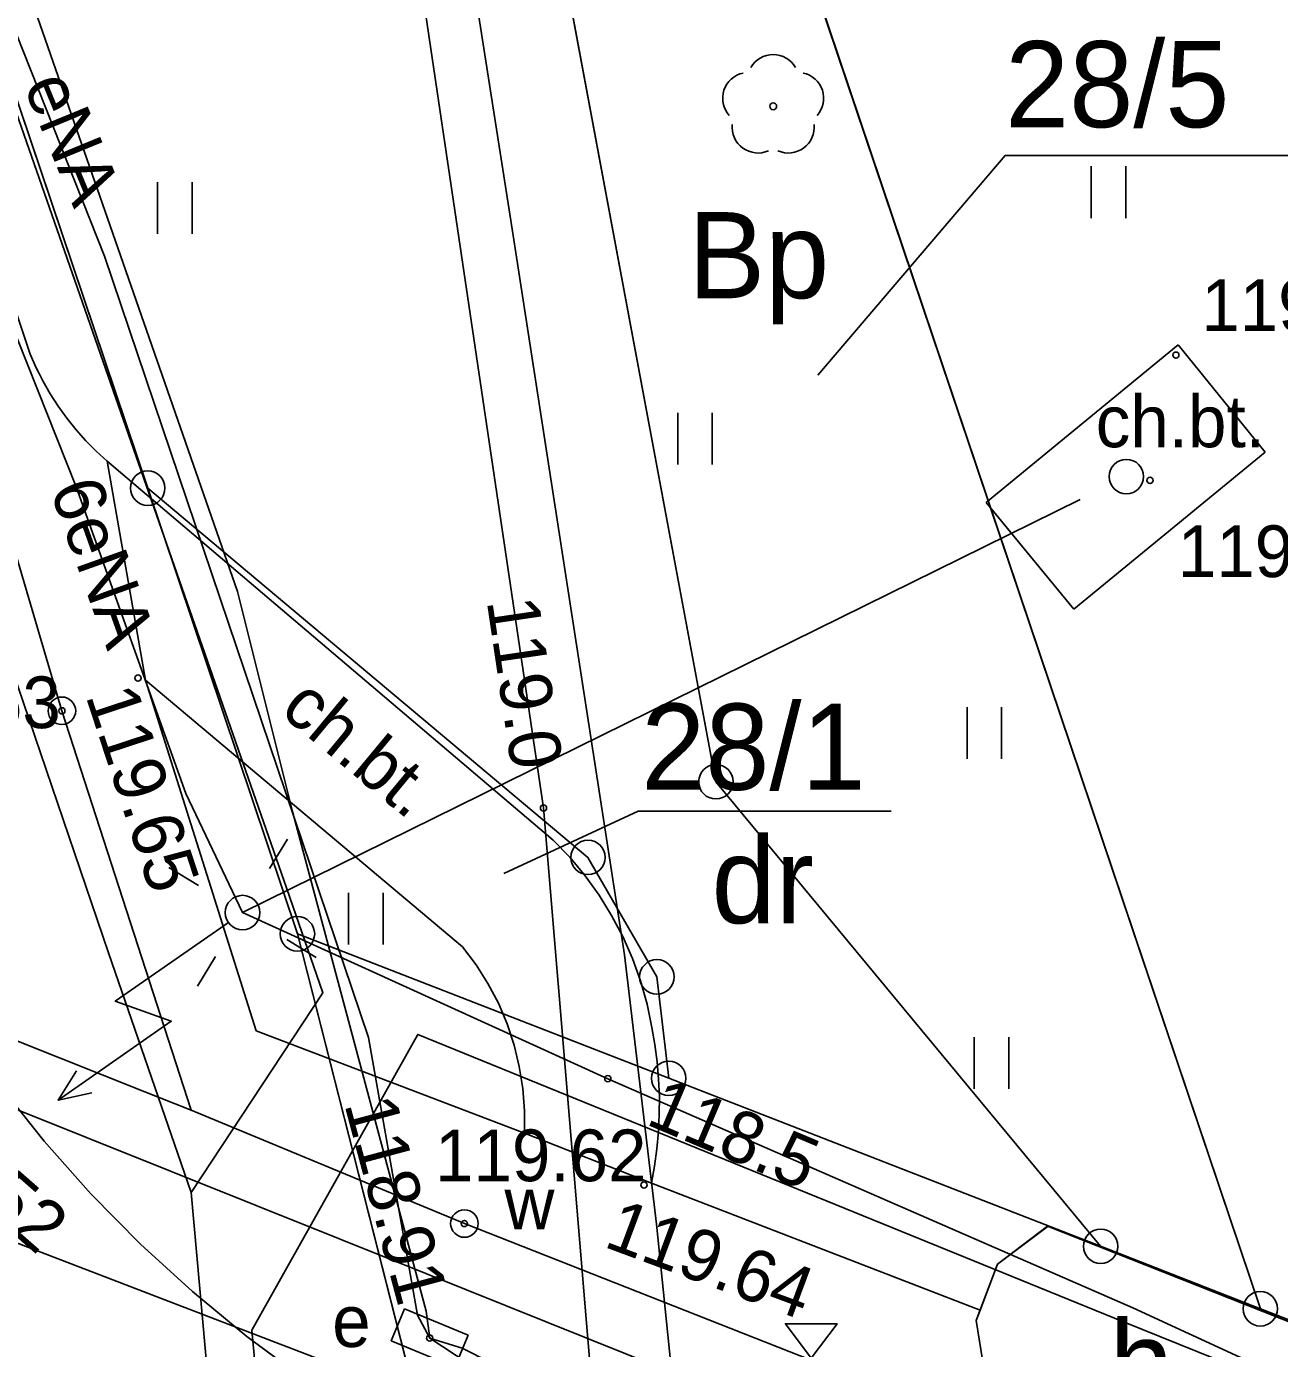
# Model space of a CAD drawing. Extents: x 6432121 to 6432331, y 5662538 to 5662686.
# Drawn here: x 6432285.88 to 6432304.05, y 5662571.21 to 5662590.39 of the extents above; entities that cross this region are included whole.
import ezdxf

# ---------------------------------------------------------------- set-up
doc = ezdxf.new("R2010")
doc.units = 0
for name, color, linetype in [('Warstwa 1', 7, 'Continuous'), ('Warstwa 10', 7, 'Continuous'), ('Warstwa 11', 7, 'Continuous'), ('Warstwa 12', 7, 'Continuous'), ('Warstwa 13', 7, 'Continuous'), ('Warstwa 14', 7, 'Continuous'), ('Warstwa 15', 7, 'Continuous'), ('Warstwa 2', 7, 'Continuous'), ('Warstwa 23', 7, 'Continuous'), ('Warstwa 25', 7, 'Continuous'), ('Warstwa 3', 7, 'Continuous'), ('Warstwa 4', 7, 'Continuous'), ('Warstwa 40', 7, 'Continuous'), ('Warstwa 5', 7, 'Continuous'), ('Warstwa 6', 7, 'Continuous'), ('Warstwa 8', 7, 'Continuous'), ('Warstwa 9', 7, 'Continuous')]:
    doc.layers.add(name, color=color, linetype=linetype)

msp = doc.modelspace()

# ---------------------------------------------------------------- linework, layer by layer
at = {"layer": 'Warstwa 1'}
for p, q in [((6432267.75, 5662642.76), (6432287.64, 5662583.69)), ((6432267.75, 5662642.76), (6432287.64, 5662583.69)), ((6432289.26, 5662614.9), (6432303.776, 5662571.783)), ((6432289.26, 5662614.9), (6432295.88, 5662579.43)), ((6432289.26, 5662614.9), (6432295.88, 5662579.43)), ((6432289.26, 5662614.9), (6432303.776, 5662571.783)), ((6432287.64, 5662583.69), (6432289.811, 5662577.223)), ((6432287.64, 5662583.69), (6432294.025, 5662578.332)), ((6432287.64, 5662583.69), (6432294.025, 5662578.332)), ((6432287.64, 5662583.69), (6432289.811, 5662577.223)), ((6432295.88, 5662579.43), (6432301.46, 5662572.69)), ((6432295.88, 5662579.43), (6432301.46, 5662572.69)), ((6432294.025, 5662578.332), (6432295.024, 5662576.599)), ((6432294.025, 5662578.332), (6432295.024, 5662576.599)), ((6432289.811, 5662577.223), (6432295.196, 5662575.127)), ((6432289.811, 5662577.223), (6432295.199, 5662556.053)), ((6432289.811, 5662577.223), (6432295.196, 5662575.127)), ((6432289.811, 5662577.223), (6432295.199, 5662556.053)), ((6432295.024, 5662576.599), (6432295.196, 5662575.127)), ((6432295.024, 5662576.599), (6432295.196, 5662575.127)), ((6432295.196, 5662575.127), (6432301.46, 5662572.69)), ((6432295.196, 5662575.127), (6432301.46, 5662572.69)), ((6432301.46, 5662572.69), (6432303.776, 5662571.783)), ((6432301.46, 5662572.69), (6432303.776, 5662571.783)), ((6432303.776, 5662571.783), (6432317.37, 5662566.48)), ((6432303.776, 5662571.783), (6432317.37, 5662566.48))]:
    msp.add_line(p, q, dxfattribs=at)
msp.add_lwpolyline([(6432300.691, 5662572.98), (6432304.313, 5662571.546), (6432304.463, 5662570.674), (6432304.083, 5662569.879), (6432303.446, 5662569.277), (6432299.793, 5662570.741), (6432299.654, 5662571.613), (6432299.964, 5662572.429)], close=True, dxfattribs=at)
msp.add_circle((6432301.833, 5662583.857), 0.25, dxfattribs=at)
at = {"layer": 'Warstwa 10'}
for points in [[(6432296.79, 5662556.053), (6432296.201, 5662561.437), (6432295.017, 5662573.011), (6432294.553, 5662576.918), (6432292.907, 5662587.574), (6432290.887, 5662600.464), (6432288.429, 5662616.311), (6432287.139, 5662624.307), (6432286.336, 5662633.904), (6432285.897, 5662641.637), (6432285.792, 5662648.915), (6432285.649, 5662654.781), (6432285.519, 5662656.344), (6432285.415, 5662656.517), (6432289.838, 5662661.556), (6432292.019, 5662663.878), (6432295.895, 5662667.79), (6432302.762, 5662670.351), (6432309.086, 5662672.408), (6432310.267, 5662672.779), (6432314.604, 5662673.152), (6432325.606, 5662675.971), (6432325.976, 5662676.047)], [(6432325.976, 5662561.918), (6432323.879, 5662562.731), (6432316.352, 5662565.671), (6432308.513, 5662568.879), (6432301.793, 5662571.593), (6432291.556, 5662575.763), (6432289.152, 5662571.474), (6432290.322, 5662558.979), (6432290.608, 5662556.053)]]:
    msp.add_lwpolyline(points, dxfattribs=at)
for centre in [(6432287.64, 5662583.69), (6432295.88, 5662579.43), (6432294.025, 5662578.332), (6432289.811, 5662577.223), (6432295.024, 5662576.599), (6432295.196, 5662575.127), (6432301.46, 5662572.69), (6432303.776, 5662571.783)]:
    msp.add_circle(centre, 0.25, dxfattribs=at)
at = {"layer": 'Warstwa 11'}
msp.add_circle((6432296.711, 5662589.23), 0.05, dxfattribs=at)
for centre, start, end in [((6432296.711, 5662589.605), 30.1471, 149.8529), ((6432296.354, 5662589.346), 102.1471, 221.8529), ((6432297.068, 5662589.346), 318.1471, 77.8529), ((6432296.491, 5662588.927), 174.1471, 293.8529), ((6432296.931, 5662588.927), 246.1471, 5.8529)]:
    msp.add_arc(centre, 0.375, start, end, dxfattribs=at)
at = {"layer": 'Warstwa 12'}
for points in [[(6432259.267, 5662681.053), (6432259.329, 5662671.143), (6432259.331, 5662662.919), (6432260.078, 5662660.682), (6432263.877, 5662649.208), (6432267.527, 5662638.022), (6432271.438, 5662626.054), (6432273.548, 5662619.652), (6432276.516, 5662610.473), (6432279.664, 5662600.926), (6432282.613, 5662591.736), (6432284.976, 5662585.268), (6432286.395, 5662580.459), (6432288.268, 5662574.665)], [(6432288.269, 5662573.47), (6432290.18, 5662576.365), (6432289.651, 5662577.89), (6432283.657, 5662595.089), (6432278.636, 5662609.529), (6432275.228, 5662619.384), (6432273.259, 5662625.008), (6432269.06, 5662637.307), (6432265.455, 5662647.676), (6432262.131, 5662657.28), (6432261.494, 5662659.216), (6432262.228, 5662660.626), (6432262.598, 5662661.472), (6432263.21, 5662662.431), (6432263.592, 5662662.793), (6432265.636, 5662665.038), (6432264.282, 5662671.637), (6432263.631, 5662675.181), (6432263.032, 5662678.117), (6432262.911, 5662681.053)], [(6432295.301, 5662556.053), (6432293.38, 5662579.05), (6432287.4, 5662619.36), (6432278, 5662645.83), (6432280.48, 5662651.78), (6432284.95, 5662659.55), (6432287.83, 5662661.59), (6432289.41, 5662662.88), (6432294.04, 5662666.15), (6432294.57, 5662666.58), (6432295.66, 5662667.86), (6432303.71, 5662670.68), (6432307.18, 5662671.52), (6432309.43, 5662672.69), (6432315.26, 5662674.17), (6432317.7, 5662674.35), (6432325.976, 5662676.304)], [(6432261.338, 5662662.021), (6432260.831, 5662661.256), (6432261.33, 5662655.003), (6432261.566, 5662651.833), (6432262.397, 5662649.473), (6432263.18, 5662647.177), (6432265.745, 5662639.575), (6432268.331, 5662631.988), (6432271.28, 5662623.264), (6432274.385, 5662614.242), (6432277.778, 5662604.216), (6432280.796, 5662595.387), (6432284.518, 5662584.444), (6432287.071, 5662576.95), (6432288.269, 5662573.47)], [(6432294.644, 5662569.974), (6432292.199, 5662571.213), (6432291.73, 5662571.359), (6432291.554, 5662571.691), (6432290.843, 5662575.72), (6432287.011, 5662587.057), (6432285.41, 5662591.097), (6432281.352, 5662603.627), (6432279.346, 5662609.722), (6432279.211, 5662610.184), (6432279.026, 5662610.616), (6432274.158, 5662623.936), (6432272.237, 5662630.449), (6432265.984, 5662647.596), (6432266.37, 5662648.378)], [(6432291.73, 5662571.359), (6432291.68, 5662571.75), (6432289.74, 5662579), (6432288.94, 5662582.19), (6432279.33, 5662609.79), (6432279.211, 5662610.184), (6432278.94, 5662610.85), (6432266.32, 5662647.75), (6432266.37, 5662648.378)], [(6432284.529, 5662588.89), (6432285.324, 5662586.912), (6432286.601, 5662583.708), (6432288.192, 5662579.261), (6432289.015, 5662577.532), (6432294.313, 5662575.121), (6432301.928, 5662571.798), (6432305.283, 5662570.247), (6432308.513, 5662568.879)], [(6432288.268, 5662574.665), (6432287.596, 5662574.929), (6432279.572, 5662578.128), (6432271.367, 5662581.39), (6432268.733, 5662580.715)], [(6432268.423, 5662579.446), (6432268.914, 5662579.286), (6432283.177, 5662573.724), (6432291.711, 5662570.445), (6432298.653, 5662567.696), (6432305.047, 5662565.259), (6432317.636, 5662560.353), (6432325.976, 5662557.133)], [(6432284.284, 5662575.255), (6432291.672, 5662572.293), (6432300.987, 5662568.554), (6432313.035, 5662563.657), (6432322.464, 5662559.942), (6432325.786, 5662558.712), (6432325.976, 5662558.636)], [(6432288.268, 5662574.665), (6432292.233, 5662573.02), (6432298.794, 5662570.433), (6432309.191, 5662566.383), (6432315.777, 5662563.747), (6432316.564, 5662563.399), (6432325.976, 5662559.685)], [(6432288.269, 5662573.47), (6432288.843, 5662567.07), (6432289.496, 5662558.647), (6432289.7, 5662556.053)], [(6432325.976, 5662557.843), (6432309.81, 5662563.98), (6432305.75, 5662565.86), (6432304.31, 5662565.79), (6432293.81, 5662569.99), (6432291.73, 5662571.359)]]:
    msp.add_lwpolyline(points, dxfattribs=at)
at = {"layer": 'Warstwa 14'}
for centre in [(6432286.395, 5662580.459), (6432293.38, 5662579.05), (6432294.313, 5662575.121), (6432292.233, 5662573.02), (6432291.73, 5662571.359), (6432291.73, 5662571.359), (6432291.73, 5662571.359)]:
    msp.add_circle(centre, 0.045, dxfattribs=at)
at = {"layer": 'Warstwa 15'}
for points in [[(6432304.326, 5662588.514), (6432300.074, 5662588.514), (6432297.358, 5662585.33)], [(6432298.424, 5662579.005), (6432294.754, 5662579.005), (6432292.806, 5662578.098)]]:
    msp.add_lwpolyline(points, dxfattribs=at)
at = {"layer": 'Warstwa 2'}
msp.add_lwpolyline([(6432298.424, 5662579.005), (6432294.754, 5662579.005), (6432292.806, 5662578.098)], dxfattribs=at)
msp.add_circle((6432289.015, 5662577.532), 0.25, dxfattribs=at)
at = {"layer": 'Warstwa 23'}
msp.add_lwpolyline([(6432289.015, 5662577.532), (6432301.165, 5662583.527)], dxfattribs=at)
at = {"layer": 'Warstwa 25'}
for centre in [(6432302.551, 5662585.62), (6432302.177, 5662583.802), (6432287.499, 5662580.934), (6432294.837, 5662573.579)]:
    msp.add_circle(centre, 0.045, dxfattribs=at)
at = {"layer": 'Warstwa 4'}
for points in [[(6432289.406, 5662578.172), (6432289.667, 5662578.599)], [(6432288.375, 5662577.923), (6432287.948, 5662578.184)], [(6432289.655, 5662577.141), (6432290.082, 5662576.88)], [(6432288.624, 5662576.892), (6432288.363, 5662576.465)]]:
    msp.add_lwpolyline(points, dxfattribs=at)
msp.add_lwpolyline([(6432292.288, 5662571.399), (6432291.364, 5662571.781), (6432291.172, 5662571.319), (6432292.096, 5662570.937)], close=True, dxfattribs=at)
for centre in [(6432286.395, 5662580.459), (6432292.233, 5662573.02)]:
    msp.add_circle(centre, 0.2, dxfattribs=at)
at = {"layer": 'Warstwa 40'}
for points in [[(6432288.81, 5662577.389), (6432287.17, 5662576.244), (6432287.981, 5662575.956), (6432286.34, 5662574.812)], [(6432286.83, 5662574.915), (6432286.34, 5662574.812), (6432286.606, 5662575.236)]]:
    msp.add_lwpolyline(points, dxfattribs=at)
msp.add_lwpolyline([(6432297.263, 5662571.067), (6432296.888, 5662571.567), (6432297.638, 5662571.567)], close=True, dxfattribs=at)
msp.add_circle((6432289.015, 5662577.532), 0.25, dxfattribs=at)
at = {"layer": 'Warstwa 5'}
for p, q in [((6432278.892, 5662645.679), (6432299.828, 5662583.507)), ((6432278.892, 5662645.679), (6432299.828, 5662583.507)), ((6432281.622, 5662598.544), (6432285.935, 5662585.632)), ((6432301.323, 5662587.609), (6432301.323, 5662588.359)), ((6432301.823, 5662587.609), (6432301.823, 5662588.359)), ((6432287.784, 5662587.378), (6432287.784, 5662588.128)), ((6432288.284, 5662587.378), (6432288.284, 5662588.128)), ((6432299.828, 5662583.507), (6432302.586, 5662585.768)), ((6432302.586, 5662585.768), (6432303.847, 5662584.213)), ((6432285.935, 5662585.632), (6432286.022, 5662585.436)), ((6432286.022, 5662585.436), (6432286.063, 5662585.355)), ((6432286.063, 5662585.355), (6432286.119, 5662585.245)), ((6432286.119, 5662585.245), (6432286.226, 5662585.059)), ((6432286.226, 5662585.059), (6432286.342, 5662584.879)), ((6432286.342, 5662584.879), (6432286.468, 5662584.705)), ((6432286.468, 5662584.705), (6432286.601, 5662584.538)), ((6432295.328, 5662584.032), (6432295.328, 5662584.782)), ((6432295.828, 5662584.032), (6432295.828, 5662584.782)), ((6432286.601, 5662584.538), (6432286.744, 5662584.377)), ((6432286.744, 5662584.377), (6432286.894, 5662584.225)), ((6432286.894, 5662584.225), (6432287.052, 5662584.08)), ((6432301.069, 5662581.936), (6432303.847, 5662584.213)), ((6432287.052, 5662584.08), (6432293.52, 5662578.584)), ((6432299.798, 5662583.482), (6432299.828, 5662583.507)), ((6432299.798, 5662583.482), (6432299.863, 5662583.403)), ((6432299.863, 5662583.403), (6432303.776, 5662571.783)), ((6432299.863, 5662583.403), (6432301.069, 5662581.936)), ((6432299.863, 5662583.403), (6432303.776, 5662571.783)), ((6432287.608, 5662580.906), (6432289.214, 5662575.814)), ((6432287.608, 5662580.906), (6432292.207, 5662577.033)), ((6432299.523, 5662579.762), (6432299.523, 5662580.512)), ((6432300.023, 5662579.762), (6432300.023, 5662580.512)), ((6432293.52, 5662578.584), (6432293.76, 5662578.334)), ((6432293.76, 5662578.334), (6432293.982, 5662578.067)), ((6432293.982, 5662578.067), (6432294.185, 5662577.785)), ((6432290.554, 5662577.069), (6432290.554, 5662577.819)), ((6432291.054, 5662577.069), (6432291.054, 5662577.819)), ((6432294.185, 5662577.785), (6432294.368, 5662577.49)), ((6432294.368, 5662577.49), (6432294.53, 5662577.183)), ((6432292.207, 5662577.033), (6432292.402, 5662576.775)), ((6432294.53, 5662577.183), (6432294.669, 5662576.866)), ((6432294.669, 5662576.866), (6432294.787, 5662576.539)), ((6432292.402, 5662576.775), (6432292.574, 5662576.501)), ((6432292.574, 5662576.501), (6432292.725, 5662576.215)), ((6432294.787, 5662576.539), (6432294.881, 5662576.205)), ((6432292.725, 5662576.215), (6432292.851, 5662575.917)), ((6432294.881, 5662576.205), (6432294.952, 5662575.865)), ((6432292.851, 5662575.917), (6432292.953, 5662575.61)), ((6432294.952, 5662575.865), (6432294.995, 5662575.616)), ((6432289.214, 5662575.814), (6432293.103, 5662574.331)), ((6432299.628, 5662574.973), (6432299.628, 5662575.723)), ((6432300.128, 5662574.973), (6432300.128, 5662575.723)), ((6432292.953, 5662575.61), (6432293.029, 5662575.296)), ((6432294.995, 5662575.616), (6432295.028, 5662575.365)), ((6432293.029, 5662575.296), (6432293.08, 5662574.977)), ((6432295.028, 5662575.365), (6432295.049, 5662575.113)), ((6432295.049, 5662575.113), (6432295.06, 5662574.861)), ((6432293.08, 5662574.977), (6432293.105, 5662574.654)), ((6432295.059, 5662574.608), (6432295.06, 5662574.861)), ((6432293.103, 5662574.331), (6432293.105, 5662574.654)), ((6432295.048, 5662574.355), (6432295.059, 5662574.608)), ((6432295.025, 5662574.103), (6432295.048, 5662574.355)), ((6432294.991, 5662573.853), (6432295.025, 5662574.103)), ((6432294.947, 5662573.604), (6432294.991, 5662573.853)), ((6432294.947, 5662573.604), (6432299.711, 5662571.764)), ((6432299.964, 5662572.429), (6432300.698, 5662572.983)), ((6432300.698, 5662572.983), (6432303.776, 5662571.783)), ((6432299.711, 5662571.764), (6432299.964, 5662572.429)), ((6432303.776, 5662571.783), (6432304.308, 5662571.576))]:
    msp.add_line(p, q, dxfattribs=at)
at = {"layer": 'Warstwa 6'}
for points in [[(6432325.976, 5662612.948), (6432316.1, 5662616.8), (6432316.08, 5662616.73), (6432312.24, 5662618.23), (6432309.49, 5662630.11), (6432302.18, 5662664.8), (6432293.88, 5662662.18), (6432283.15, 5662647.61), (6432289.26, 5662614.9), (6432303.776, 5662571.783), (6432317.37, 5662566.48), (6432324.02, 5662582.95), (6432324.37, 5662582.84), (6432325.976, 5662586.89)], [(6432295.199, 5662556.053), (6432289.811, 5662577.223), (6432287.64, 5662583.69), (6432267.75, 5662642.76), (6432246.69, 5662636.13), (6432263.163, 5662588.197), (6432269.007, 5662560.534), (6432269.756, 5662556.053)], [(6432325.976, 5662563.071), (6432317.811, 5662566.312), (6432317.37, 5662566.48), (6432303.776, 5662571.783), (6432301.46, 5662572.69), (6432295.196, 5662575.127), (6432289.811, 5662577.223), (6432295.199, 5662556.053)], [(6432291.638, 5662569.69), (6432290.756, 5662570.209), (6432289.902, 5662570.773), (6432289.079, 5662571.381), (6432288.289, 5662572.032), (6432287.534, 5662572.722), (6432286.816, 5662573.451), (6432286.137, 5662574.217), (6432285.499, 5662575.017), (6432284.904, 5662575.849)]]:
    msp.add_lwpolyline(points, dxfattribs=at)
for points in [[(6432278.892, 5662645.679), (6432279.29, 5662646.39), (6432267.75, 5662642.76), (6432287.64, 5662583.69), (6432294.025, 5662578.332), (6432295.024, 5662576.599), (6432295.196, 5662575.127), (6432301.46, 5662572.69), (6432295.88, 5662579.43), (6432289.26, 5662614.9)], [(6432289.26, 5662614.9), (6432303.776, 5662571.783), (6432301.46, 5662572.69), (6432295.88, 5662579.43)], [(6432287.64, 5662583.69), (6432289.811, 5662577.223), (6432295.196, 5662575.127), (6432295.024, 5662576.599), (6432294.025, 5662578.332)]]:
    msp.add_lwpolyline(points, close=True, dxfattribs=at)
at = {"layer": 'Warstwa 8'}
for p, q in [((6432285.499, 5662575.017), (6432286.137, 5662574.217)), ((6432286.137, 5662574.217), (6432286.816, 5662573.451)), ((6432286.816, 5662573.451), (6432287.534, 5662572.722)), ((6432287.534, 5662572.722), (6432288.289, 5662572.032)), ((6432288.289, 5662572.032), (6432289.079, 5662571.381)), ((6432289.079, 5662571.381), (6432289.902, 5662570.773))]:
    msp.add_line(p, q, dxfattribs=at)
at = {"layer": 'Warstwa 9'}
for p, q in [((6432281.622, 5662598.544), (6432285.935, 5662585.632)), ((6432299.798, 5662583.482), (6432302.586, 5662585.768)), ((6432302.586, 5662585.768), (6432303.847, 5662584.213)), ((6432285.935, 5662585.632), (6432286.022, 5662585.436)), ((6432286.022, 5662585.436), (6432286.063, 5662585.355)), ((6432286.063, 5662585.355), (6432286.119, 5662585.245)), ((6432286.119, 5662585.245), (6432286.226, 5662585.059)), ((6432286.226, 5662585.059), (6432286.342, 5662584.879)), ((6432286.342, 5662584.879), (6432286.468, 5662584.705)), ((6432286.468, 5662584.705), (6432286.601, 5662584.538)), ((6432286.601, 5662584.538), (6432286.744, 5662584.377)), ((6432286.744, 5662584.377), (6432286.894, 5662584.225)), ((6432286.894, 5662584.225), (6432287.052, 5662584.08)), ((6432301.069, 5662581.936), (6432303.847, 5662584.213)), ((6432287.052, 5662584.08), (6432293.52, 5662578.584)), ((6432287.052, 5662584.08), (6432287.608, 5662580.906)), ((6432287.052, 5662584.08), (6432287.608, 5662580.906)), ((6432299.798, 5662583.482), (6432301.069, 5662581.936)), ((6432287.608, 5662580.906), (6432292.207, 5662577.033)), ((6432287.608, 5662580.906), (6432289.214, 5662575.814)), ((6432293.52, 5662578.584), (6432293.76, 5662578.334)), ((6432293.76, 5662578.334), (6432293.982, 5662578.067)), ((6432293.982, 5662578.067), (6432294.185, 5662577.785)), ((6432294.185, 5662577.785), (6432294.368, 5662577.49)), ((6432294.368, 5662577.49), (6432294.53, 5662577.183)), ((6432292.207, 5662577.033), (6432292.402, 5662576.775)), ((6432294.53, 5662577.183), (6432294.669, 5662576.866)), ((6432294.669, 5662576.866), (6432294.787, 5662576.539)), ((6432292.402, 5662576.775), (6432292.574, 5662576.501)), ((6432292.574, 5662576.501), (6432292.725, 5662576.215)), ((6432294.787, 5662576.539), (6432294.881, 5662576.205)), ((6432292.725, 5662576.215), (6432292.851, 5662575.917)), ((6432294.881, 5662576.205), (6432294.952, 5662575.865)), ((6432292.851, 5662575.917), (6432292.953, 5662575.61)), ((6432294.952, 5662575.865), (6432294.995, 5662575.616)), ((6432289.214, 5662575.814), (6432293.103, 5662574.331)), ((6432292.953, 5662575.61), (6432293.029, 5662575.296)), ((6432294.995, 5662575.616), (6432295.028, 5662575.365)), ((6432293.029, 5662575.296), (6432293.08, 5662574.977)), ((6432295.028, 5662575.365), (6432295.049, 5662575.113)), ((6432295.049, 5662575.113), (6432295.06, 5662574.861)), ((6432285.499, 5662575.017), (6432286.137, 5662574.217)), ((6432293.08, 5662574.977), (6432293.105, 5662574.654)), ((6432295.059, 5662574.608), (6432295.06, 5662574.861)), ((6432293.103, 5662574.331), (6432293.105, 5662574.654)), ((6432295.048, 5662574.355), (6432295.059, 5662574.608)), ((6432293.103, 5662574.331), (6432294.947, 5662573.604)), ((6432293.103, 5662574.331), (6432294.947, 5662573.604)), ((6432295.025, 5662574.103), (6432295.048, 5662574.355)), ((6432286.137, 5662574.217), (6432286.816, 5662573.451)), ((6432294.991, 5662573.853), (6432295.025, 5662574.103)), ((6432294.947, 5662573.604), (6432294.991, 5662573.853)), ((6432294.947, 5662573.604), (6432299.711, 5662571.764)), ((6432286.816, 5662573.451), (6432287.534, 5662572.722)), ((6432287.534, 5662572.722), (6432288.289, 5662572.032)), ((6432288.289, 5662572.032), (6432289.079, 5662571.381)), ((6432299.654, 5662571.613), (6432299.711, 5662571.764)), ((6432299.654, 5662571.613), (6432299.793, 5662570.741)), ((6432289.079, 5662571.381), (6432289.902, 5662570.773))]:
    msp.add_line(p, q, dxfattribs=at)

# ---------------------------------------------------------------- texts
at = {"layer": 'Warstwa 13'}
for s, rotation, p in [('eNA', 292.3173, (6432285.833, 5662589.534)), ('6eNA', 289.6875, (6432286.214, 5662583.675))]:
    msp.add_text(s, height=0.75, rotation=rotation, dxfattribs=at).set_placement(p)
at = {"layer": 'Warstwa 14'}
for s, rotation, p in [('119.0', 278.4403, (6432292.555, 5662582.055)), ('118.5', 337.1226, (6432294.844, 5662574.468)), ('118.91', 284.9777, (6432290.488, 5662574.756))]:
    msp.add_text(s, height=0.75, rotation=rotation, dxfattribs=at).set_placement(p)
at = {"layer": 'Warstwa 15'}
for s, height, p in [('28/5', 1.25, (6432300.074, 5662588.926)), ('119.63', 0.75, (6432283.312, 5662580.208)), ('28/1', 1.25, (6432294.797, 5662579.313)), ('119.62', 0.75, (6432291.806, 5662573.634))]:
    msp.add_text(s, height=height, dxfattribs=at).set_placement(p)
at = {"layer": 'Warstwa 2'}
for s, p in [('Bp', (6432295.479, 5662586.445)), ('dr', (6432295.817, 5662577.377))]:
    msp.add_text(s, height=1.25, dxfattribs=at).set_placement(p)
at = {"layer": 'Warstwa 25'}
for s, p in [('119.54', (6432302.919, 5662585.97)), ('119.62', (6432302.579, 5662582.399))]:
    msp.add_text(s, height=0.75, dxfattribs=at).set_placement(p)
for s, rotation, p in [('119.65', 288.2035, (6432286.735, 5662580.679)), ('119.52', 318.788, (6432283.744, 5662574.57)), ('119.64', 339.5921, (6432294.234, 5662572.69))]:
    msp.add_text(s, height=0.75, rotation=rotation, dxfattribs=at).set_placement(p)
at = {"layer": 'Warstwa 3'}
msp.add_text('h', height=1.25, dxfattribs=at).set_placement((6432301.584, 5662570.364))
at = {"layer": 'Warstwa 5'}
for s, p in [('w', (6432292.814, 5662572.936)), ('e', (6432290.315, 5662571.229))]:
    msp.add_text(s, height=0.75, dxfattribs=at).set_placement(p)
at = {"layer": 'Warstwa 9'}
msp.add_text('ch.bt.', height=0.75, dxfattribs=at).set_placement((6432301.389, 5662584.283))
msp.add_text('ch.bt.', height=0.75, rotation=320.3464, dxfattribs=at).set_placement((6432289.538, 5662580.428))

doc.saveas('drawing.dxf')
